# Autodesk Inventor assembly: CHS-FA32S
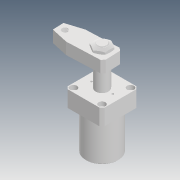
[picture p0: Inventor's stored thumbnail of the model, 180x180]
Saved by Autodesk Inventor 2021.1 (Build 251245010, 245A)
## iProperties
Created: 2019-04
Part Number: CHS-FA32S
Description: STEP AP203
Document SubType Name: Assembly
Designer: user
Title: chs-fa32s_asm.STEP
Revision Number: ÈÎºÎ
Sending System: SolidWorks 2017
Preprocessor: SwSTEP 2.0
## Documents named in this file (5)
- D:\Vault_2016\Projekty\Clamptek\Hydraulic\CHS\CHS-32\Inventor\CHS-FA32S\CHS-FA32S.iam
- D:\Vault_2016\Projekty\Clamptek\Hydraulic\CHS\CHS-32\Inventor\CHS-FA32S\CHS-32S-02_1.ipt
- D:\Vault_2016\Projekty\Clamptek\Hydraulic\CHS\CHS-32\Inventor\CHS-FA32S\CHS-32S-01_2.ipt
- D:\Vault_2016\Projekty\Clamptek\Hydraulic\CHS\CHS-32\Inventor\CHS-FA32S\M16_2.ipt
- D:\Vault_2016\Projekty\Clamptek\Hydraulic\CHS\CHS-32\Inventor\CHS-FA32S\CHS-FA32BT.ipt
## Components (4 placed, 4 different names)
1. CHS-32S-02_1_1
2. CHS-32S-01_2_2
3. M16_2_3
4. CHS-FA32BT_4
